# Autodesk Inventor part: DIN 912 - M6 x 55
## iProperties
IsCustomPart: 1
Created: 2006-02
Part Number: DIN 912 - M6 x 55
Material: Steel, Mild
Description: Cylinder Head Cap Screw
Document SubType Name: Modeling
Standard: DIN 912
Designer: Andy Moles
Standards Organization: DIN
Language: en-US
Size Designation: M6 x 55
Categories: <MemberInstance><Categories><Category DisplayName="Fasteners" InternalName="e4da775c-781d-43d5-af7c-5136215cf5a6" Mnemonic="FSTN"><Category DisplayName="Bolts"
Density: 1 g/cm^3
Author: Andy Moles
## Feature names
1. Body [Revolution]
2. Slot [Extrusion]
3. Fillet1
4. Chamfer1
